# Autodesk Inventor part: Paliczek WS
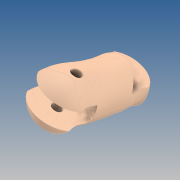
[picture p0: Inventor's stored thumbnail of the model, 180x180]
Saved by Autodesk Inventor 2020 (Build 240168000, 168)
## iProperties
Created: 2019-10
Part Number: Paliczek WS
Material: GFRP
Document SubType Name: Modeling
Designer: yello
Density: 1.75 g/cm^3
Appearance: Default
Author: yello
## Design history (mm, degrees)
feature "Paliczek WS"
sketch "Sketch1"
  geometry: C1 r 2 at (0, 0); 1 further point
  constraints: 1 centre point
  dimensions: "d0" = 4 diameter of C1
extrude "Extrusion1" cut sketch "Sketch1" stored distance "d1" = 100; taper "d2" = 0 deg
body "Solid1"
